// Mitsubishi GX Works2 project: 读写时钟指令   PLC: FX3U/FX3UC

PROGRAM MAIN
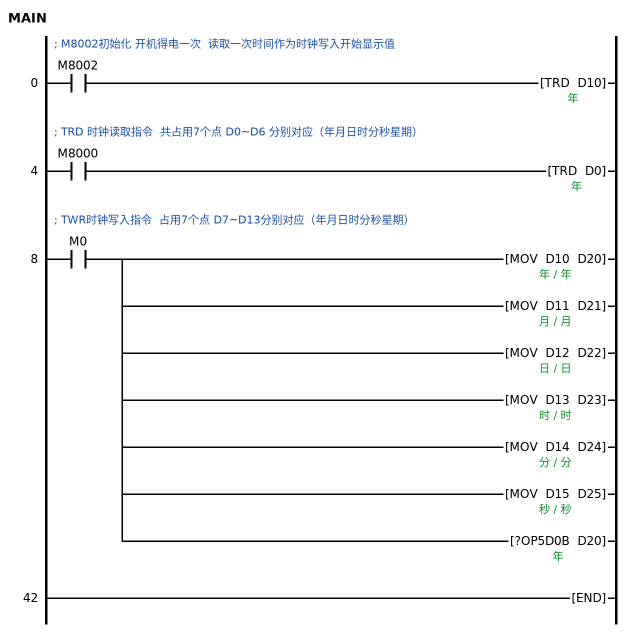
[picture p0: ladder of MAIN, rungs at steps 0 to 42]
; M8002初始化 开机得电一次  读取一次时间作为时钟写入开始显示值
0     LD      M8002
      TRD     D10  ; 年
; TRD 时钟读取指令  共占用7个点 D0~D6 分别对应（年月日时分秒星期）
4     LD      M8000
      TRD     D0  ; 年
; TWR时钟写入指令  占用7个点 D7~D13分别对应（年月日时分秒星期）
8     LD      M0
      MOV     D10 D20  ; 年
      MOV     D11 D21  ; 月 / 月
      MOV     D12 D22  ; 日 / 日
      MOV     D13 D23  ; 时 / 时
      MOV     D14 D24  ; 分 / 分
      MOV     D15 D25  ; 秒 / 秒
      ?OP5D0B D20
42    END
END_PROGRAM

// device comments not shown above
D6  ; 星期
D1  ; 月
D2  ; 日
D3  ; 时
D4  ; 分
D5  ; 秒
D16  ; 星期
D26  ; 星期
